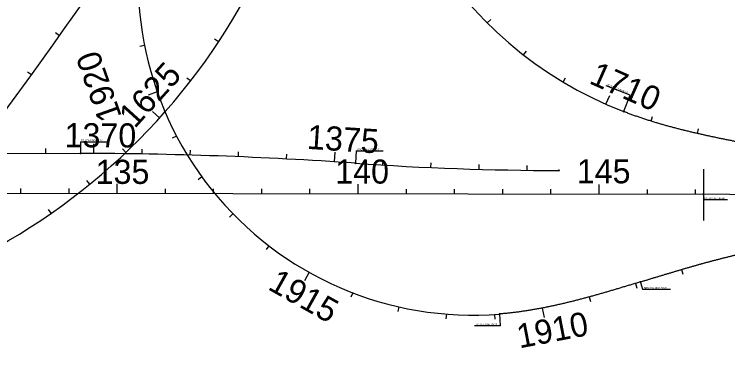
# Model space of a CAD drawing. Extents: x 448091 to 665917, y 1461380 to 1587607.
# Drawn here: x 485717 to 487198, y 1570129 to 1570850 of the extents above; entities that cross this region are included whole.
import ezdxf

# ---------------------------------------------------------------- set-up
doc = ezdxf.new("R2010")
doc.units = 0
for name, color, linetype in [('AttenuatorTM', 7, 'Continuous'), ('BarrierWall_ep', 7, 'Continuous'), ('BillboardVeg', 7, 'Continuous'), ('BillboardZone', 7, 'Continuous'), ('BLSurvey_dp', 7, 'Continuous'), ('BLSurveyCntrl_ep', 7, 'Continuous'), ('BLSurveyField_ep', 7, 'Continuous'), ('BLSurveySymbl_ep', 7, 'Continuous'), ('BoxCulvert', 7, 'Continuous')]:
    doc.layers.add(name, color=color, linetype=linetype)

msp = doc.modelspace()

# ---------------------------------------------------------------- linework, layer by layer
at = {"layer": 'AttenuatorTM'}
for p, q in [((486995.2, 1570682.3), (486945.4, 1570701.6)), ((486982.4, 1570649.3), (486995.2, 1570682.3)), ((486982, 1570648.3), (486982.9, 1570650.7)), ((485855, 1570585.9), (485854.9, 1570561.6)), ((485855, 1570585.9), (485909.9, 1570585.9)), ((486427.1, 1570566.9), (486425.3, 1570541.3)), ((486427.1, 1570566.9), (486483, 1570566.8)), ((487147.5, 1570475.8), (487147.5, 1570465.8)), ((487147.5, 1570465.8), (487197.3, 1570465.7)), ((487016.8, 1570294.1), (487021.2, 1570279.9)), ((487021.2, 1570279.9), (487079.2, 1570279.7)), ((486726.7, 1570203.8), (486724.7, 1570228.5)), ((486726.7, 1570203.8), (486672.6, 1570203.9))]:
    msp.add_line(p, q, dxfattribs=at)
for centre in [(486982, 1570648.3), (485854.9, 1570561.6), (486425.3, 1570541.3), (486847.5, 1570526.3), (487147.5, 1570476.8), (487016.6, 1570295.1), (486724.7, 1570228.5)]:
    msp.add_circle(centre, 1, dxfattribs=at)
at = {"layer": 'BarrierWall_ep'}
msp.add_line((487147.5, 1570529.3), (487147.4, 1570422.2), dxfattribs=at)
at = {"layer": 'BillboardVeg'}
msp.add_line((483831.1, 1570481.4), (487147.5, 1570476.8), dxfattribs=at)
msp.add_arc((487141.7, 1566306.8), 4170, 43.0411, 89.9208, dxfattribs=at)
at = {"layer": 'BLSurvey_dp'}
for p, q in [((485931.1, 1570478.5), (485931.1, 1570498.5)), ((486431.1, 1570477.8), (486431.1, 1570497.8)), ((486931.1, 1570477.1), (486931.1, 1570497.1)), ((485731.1, 1570478.8), (485731.1, 1570488.8)), ((485831.1, 1570478.7), (485831.1, 1570488.7)), ((486031.1, 1570478.4), (486031.1, 1570488.4)), ((486131.1, 1570478.2), (486131.1, 1570488.2)), ((486231.1, 1570478.1), (486231.1, 1570488.1)), ((486331.1, 1570478), (486331.1, 1570488)), ((486531.1, 1570477.7), (486531.1, 1570487.7)), ((486631.1, 1570477.6), (486631.1, 1570487.6)), ((486731.1, 1570477.4), (486731.1, 1570487.4)), ((486831.1, 1570477.3), (486831.1, 1570487.3)), ((487031.1, 1570477), (487031.1, 1570487)), ((487131.1, 1570476.9), (487131.1, 1570486.9))]:
    msp.add_line(p, q, dxfattribs=at)
at = {"layer": 'BLSurveyCntrl_ep'}
msp.add_line((483417.5, 1570565), (485854.9, 1570561.6), dxfattribs=at)
for centre, radius, start, end in [((487277.4, 1571412.2), 819, 171.7918, 248.8601), ((486668.9, 1570920.7), 694.5, 162.6203, 274.6039), ((484878.9, 1571722.2), 1145.9, 274.6708, 323.1235), ((485039.7, 1571520.5), 1320, 262.0169, 336.3064), ((485843.4, 1562224.6), 8337, 85.99748, 89.92084), ((486856.1, 1576697.2), 6171, 265.99748, 269.92084)]:
    msp.add_arc(centre, radius, start, end, dxfattribs=at)
for points in [[(487272.5, 1570575.2), (487268.5, 1570575.9), (487264.5, 1570576.7), (487260.5, 1570577.4), (487256.6, 1570578.2), (487252.6, 1570578.9), (487248.6, 1570579.7), (487244.6, 1570580.4), (487240.6, 1570581.2), (487236.6, 1570581.9), (487232.7, 1570582.7), (487228.7, 1570583.5), (487224.7, 1570584.2), (487220.7, 1570585), (487216.7, 1570585.8), (487212.8, 1570586.5), (487208.8, 1570587.3), (487204.8, 1570588.1), (487200.8, 1570588.9), (487196.9, 1570589.7), (487192.9, 1570590.5), (487188.9, 1570591.3), (487184.9, 1570592.1), (487181, 1570592.9), (487177, 1570593.7), (487173, 1570594.6), (487169.1, 1570595.4), (487165.1, 1570596.2), (487161.1, 1570597.1), (487157.2, 1570598), (487153.2, 1570598.8), (487149.3, 1570599.7), (487145.3, 1570600.6), (487141.3, 1570601.5), (487137.4, 1570602.4), (487133.4, 1570603.3), (487129.5, 1570604.2), (487125.5, 1570605.1), (487121.6, 1570606), (487117.7, 1570607), (487113.7, 1570607.9), (487109.8, 1570608.9), (487105.8, 1570609.9), (487101.9, 1570610.9), (487098, 1570611.9), (487094.1, 1570612.9), (487090.1, 1570613.9), (487086.2, 1570614.9), (487082.3, 1570616), (487078.4, 1570617.1), (487074.5, 1570618.1), (487070.6, 1570619.2), (487066.7, 1570620.3), (487062.8, 1570621.4), (487058.9, 1570622.5), (487055, 1570623.7), (487051.1, 1570624.8), (487047.2, 1570626), (487043.3, 1570627.2), (487039.5, 1570628.4), (487035.6, 1570629.6), (487031.7, 1570630.8), (487027.9, 1570632.1), (487024, 1570633.3), (487020.2, 1570634.6), (487016.3, 1570635.9), (487012.5, 1570637.2), (487008.7, 1570638.6), (487004.8, 1570639.9), (487001, 1570641.3), (486997.2, 1570642.6), (486993.4, 1570644), (486989.6, 1570645.5), (486985.8, 1570646.9), (486982, 1570648.3)], [(487016.6, 1570295.1), (487019.8, 1570296.1), (487023, 1570297.1), (487026.2, 1570298.1), (487029.5, 1570299), (487032.7, 1570300), (487035.9, 1570301), (487039.2, 1570302), (487042.4, 1570303), (487045.6, 1570304), (487048.9, 1570304.9), (487052.1, 1570305.9), (487055.3, 1570306.9), (487058.6, 1570307.9), (487061.8, 1570308.9), (487065, 1570309.8), (487068.3, 1570310.8), (487071.5, 1570311.8), (487074.7, 1570312.7), (487078, 1570313.7), (487081.2, 1570314.7), (487084.5, 1570315.6), (487087.7, 1570316.6), (487090.9, 1570317.6), (487094.2, 1570318.5), (487097.4, 1570319.5), (487100.7, 1570320.4), (487103.9, 1570321.4), (487107.1, 1570322.3), (487110.4, 1570323.3), (487113.6, 1570324.2), (487116.9, 1570325.1), (487120.1, 1570326.1), (487123.4, 1570327), (487126.6, 1570327.9), (487129.9, 1570328.8), (487133.1, 1570329.8), (487136.4, 1570330.7), (487139.6, 1570331.6), (487142.9, 1570332.5), (487146.1, 1570333.4), (487149.4, 1570334.3), (487152.7, 1570335.2), (487155.9, 1570336.1), (487159.2, 1570336.9), (487162.4, 1570337.8), (487165.7, 1570338.7), (487169, 1570339.6), (487172.2, 1570340.4), (487175.5, 1570341.3), (487178.8, 1570342.1), (487182, 1570343), (487185.3, 1570343.8), (487188.6, 1570344.7), (487191.9, 1570345.5), (487195.1, 1570346.3), (487198.4, 1570347.1), (487201.7, 1570347.9), (487205, 1570348.7), (487208.3, 1570349.5), (487211.5, 1570350.3), (487214.8, 1570351.1), (487218.1, 1570351.9), (487221.4, 1570352.7), (487224.7, 1570353.4), (487228, 1570354.2), (487231.3, 1570354.9), (487234.6, 1570355.7), (487237.9, 1570356.4), (487241.2, 1570357.1), (487244.5, 1570357.9), (487247.8, 1570358.6), (487251.1, 1570359.3), (487254.4, 1570360), (487257.7, 1570360.7)], [(487016.6, 1570295.1), (487012.7, 1570293.9), (487008.8, 1570292.7), (487004.9, 1570291.5), (487001, 1570290.4), (486997.2, 1570289.2), (486993.3, 1570288), (486989.4, 1570286.8), (486985.5, 1570285.7), (486981.6, 1570284.5), (486977.8, 1570283.3), (486973.9, 1570282.1), (486970, 1570281), (486966.1, 1570279.8), (486962.2, 1570278.7), (486958.3, 1570277.5), (486954.4, 1570276.4), (486950.6, 1570275.2), (486946.7, 1570274.1), (486942.8, 1570273), (486938.9, 1570271.8), (486935, 1570270.7), (486931.1, 1570269.6), (486927.2, 1570268.5), (486923.3, 1570267.4), (486919.4, 1570266.3), (486915.5, 1570265.2), (486911.6, 1570264.1), (486907.7, 1570263.1), (486903.7, 1570262), (486899.8, 1570261), (486895.9, 1570259.9), (486892, 1570258.9), (486888.1, 1570257.9), (486884.1, 1570256.9), (486880.2, 1570255.9), (486876.3, 1570254.9), (486872.3, 1570253.9), (486868.4, 1570252.9), (486864.5, 1570252), (486860.5, 1570251), (486856.6, 1570250.1), (486852.6, 1570249.2), (486848.7, 1570248.3), (486844.7, 1570247.4), (486840.8, 1570246.5), (486836.8, 1570245.6), (486832.8, 1570244.8), (486828.9, 1570244), (486824.9, 1570243.1), (486820.9, 1570242.3), (486817, 1570241.5), (486813, 1570240.8), (486809, 1570240), (486805, 1570239.3), (486801, 1570238.6), (486797, 1570237.8), (486793, 1570237.2), (486789, 1570236.5), (486785, 1570235.8), (486781, 1570235.2), (486777, 1570234.6), (486773, 1570234), (486769, 1570233.4), (486765, 1570232.9), (486761, 1570232.3), (486756.9, 1570231.8), (486752.9, 1570231.3), (486748.9, 1570230.9), (486744.9, 1570230.4), (486740.8, 1570230), (486736.8, 1570229.6), (486732.8, 1570229.2), (486728.7, 1570228.8), (486724.7, 1570228.5)]]:
    msp.add_spline(points, degree=3, dxfattribs=at)
at = {"layer": 'BLSurveyField_ep'}
for p, q in [((486699, 1570832.4), (486706.1, 1570839.4)), ((486141.3, 1570793.2), (486132.9, 1570798.7)), ((485987.7, 1570785.6), (485977.9, 1570783.7)), ((486774, 1570766.2), (486780.1, 1570774.1)), ((486083.1, 1570711.9), (486075.2, 1570718)), ((486856.4, 1570709.7), (486861.5, 1570718.3)), ((486014.2, 1570689.2), (485995.3, 1570682.6)), ((486945.1, 1570663.7), (486953.2, 1570682)), ((486018.9, 1570635.3), (486004, 1570648.7)), ((487038.7, 1570628.6), (487041.7, 1570638.2)), ((487135.3, 1570602.8), (487137.5, 1570612.6)), ((486054.1, 1570597.7), (486045.3, 1570593)), ((485882.6, 1570561.5), (485882.7, 1570581.5)), ((485782.6, 1570561.7), (485782.6, 1570571.7)), ((485949.1, 1570563.7), (485942.2, 1570570.9)), ((485982.6, 1570560.5), (485982.8, 1570570.5)), ((486082.6, 1570558.2), (486082.8, 1570568.2)), ((486182.5, 1570554.7), (486182.9, 1570564.7)), ((486282.4, 1570550.1), (486282.9, 1570560.1)), ((486382.2, 1570544.2), (486383.5, 1570564.2)), ((486482, 1570537.6), (486482.6, 1570547.6)), ((486581.9, 1570532.3), (486582.3, 1570542.3)), ((486681.8, 1570528.7), (486682.1, 1570538.7)), ((486781.8, 1570526.7), (486781.9, 1570536.7)), ((486106.9, 1570512.8), (486098.8, 1570506.9)), ((485874, 1570497.6), (485867.7, 1570505.4)), ((485794.2, 1570437.4), (485788.5, 1570445.6)), ((486171.2, 1570436.4), (486164, 1570429.4)), ((486245.9, 1570370), (486239.8, 1570362)), ((486329.3, 1570315), (486319.5, 1570297.5)), ((487102.1, 1570320.8), (487104.9, 1570311.2)), ((487006.3, 1570292), (487009.2, 1570282.4)), ((486419.7, 1570272.5), (486416.1, 1570263.2)), ((486910.4, 1570263.8), (486913, 1570254.2)), ((486515.3, 1570243.5), (486513.1, 1570233.7)), ((486813.1, 1570240.8), (486816.8, 1570221.1)), ((486614.1, 1570228.4), (486613.3, 1570218.4)), ((486714, 1570227.7), (486714.6, 1570217.7))]:
    msp.add_line(p, q, dxfattribs=at)
at = {"layer": 'BoxCulvert'}
for p, q in [((485811.4, 1570805.7), (485803.2, 1570811.5)), ((485753.2, 1570724.4), (485745.1, 1570730.3))]:
    msp.add_line(p, q, dxfattribs=at)
msp.add_arc((479569, 1575209.6), 7639.4, 310.59194, 329.29807, dxfattribs=at)

# ---------------------------------------------------------------- texts
at = {"layer": 'AttenuatorTM'}
for s, rotation, p in [('SC STA. 1709+60.00', 338.0119, (486947.2, 1570702.9)), ('PC STA 1369+72.33', 359.9208, (485856.2, 1570587.3)), ('PRC STA 1375+43.21', 359.9518, (486429.6, 1570568)), ('PC STA 147+16.38', 359.8517, (487149.6, 1570467.2)), ('SRS STA 1907+89.29', 359.9514, (487024, 1570280.9)), ('SC STA 1910+89.29', 0.1156, (486675.1, 1570205.2))]:
    msp.add_text(s, height=3.5, rotation=rotation, dxfattribs=at).set_placement(p)
at = {"layer": 'BillboardZone'}
for s, p in [('135', (485886.3, 1570498.5)), ('140', (486383.5, 1570499.1)), ('145', (486884.6, 1570499.7))]:
    msp.add_text(s, height=50, rotation=359.9208, dxfattribs=at).set_placement(p)
at = {"layer": 'BLSurveySymbl_ep'}
for s, rotation, p in [('1920', 109.4707, (485941.2, 1570638.2)), ('1625', 47.8829, (485967.4, 1570611.8)), ('1710', 336.0618, (486908, 1570708)), ('1370', 359.7307, (485821.7, 1570574.6)), ('1375', 356.2945, (486323.9, 1570571.2)), ('1915', 330.7207, (486241.5, 1570280.7)), ('1910', 10.8743, (486765.7, 1570157))]:
    msp.add_text(s, height=50, rotation=rotation, dxfattribs=at).set_placement(p)

doc.saveas('drawing.dxf')
